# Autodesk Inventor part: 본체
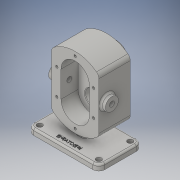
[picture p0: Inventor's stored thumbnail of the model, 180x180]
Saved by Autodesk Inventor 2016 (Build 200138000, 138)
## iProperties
Created: 2019-03
Part Number: 본체
Material: Generic
Document SubType Name: Modeling
Designer: Administrator
Density: 1 g/cm^3
Appearance: Default
Author: Administrator
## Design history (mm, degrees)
sketch "스케치1"
  geometry: L1 (60, 36.5)-(-60, 36.5); L2 (-60, 36.5)-(-60, -36.5); L3 (-60, -36.5)-(60, -36.5); L4 (60, -36.5)-(60, 36.5); L5 (60, 36.5)-(-60, -36.5); L6 (-60, 36.5)-(60, -36.5); 1 further point
  constraints: 12 end point, 2 midpoint, 2 parallel, 1 horizontal, 1 perpendicular
  dimensions: "d0" = 73 distance of L1.end L2.end; "d1" = 120 distance of L2.end L3.end
extrude "돌출1" new body sketch "스케치1" distance "d2" = 10; taper "d3" = 0 deg
node "작업 평면1"
sketch "스케치2"
  geometry: L1 (0, 0)-(0, 78); L2 (-40, 33.279)-(40, 33.279); L3 (40, 33.279)-(40, 122.721); L4 (-40, 122.721)-(-40, 33.279); L5 (-40, 33.279)-(40, 122.721); L6 (40, 33.279)-(-40, 122.721); L7 (-46.037, 78)-(46.038, 78); A1 r 60 centre (0, 78) between (40, 122.721) and (-40, 122.721); A2 r 60 centre (0, 78) between (-40, 33.279) and (40, 33.279); 2 further points
  constraints: 14 end point, 5 midpoint, 4 point on circle, 2 centre point, 2 horizontal, 1 coincident, 1 parallel, 1 perpendicular, 1 vertical
  dimensions: "d5" = 78 distance of L1.start L1.end; "d6" = 80 distance between parallel lines of L3 L4; "d7" = 60 radius of A1; "d8" = 60 radius of A2
extrude "돌출2" join sketch "스케치2" distance "d9" = 53; taper "d10" = 0 deg
sketch "스케치3"
  geometry: L1 (0, 0)-(0, 78); L2 (-54.769, 78)-(54.769, 78); L3 (0, 100)-(0, 56); L4 (-24, 100)-(-24, 56); L5 (24, 56)-(24, 100); A1 r 24 centre (0, 100) between (24, 100) and (-24, 100); A2 r 24 centre (0, 56) between (-24, 56) and (24, 56); 1 further point
  constraints: 12 end point, 4 point on circle, 4 tangent, 2 centre point, 2 midpoint, 1 coincident, 1 horizontal, 1 parallel, 1 point on line, 1 vertical
  dimensions: "d11" = 78 distance of L1.end L1.start; "d12" = 22 distance of L1.end L3.start; "d13" = 24 radius of A1
extrude "돌출3" cut sketch "스케치3" distance "d14" = 29; taper "d15" = 0 deg
sketch "스케치4"
  geometry: L1 (0, 0)-(0, 78); C1 r 12.5 at (0, 100); C2 r 12.5 at (0, 56)
  constraints: 2 centre point, 2 end point, 2 point on line, 1 equal radius, 1 vertical
  dimensions: "d16" = 78 distance of L1.start L1.end; "d17" = 22 distance of L1.end C1.centre; "d18" = 22 distance of L1.end C2.centre; "d19" = 25 diameter of C1
extrude "돌출4" cut sketch "스케치4" distance "d20" = 15; taper "d21" = 0 deg
sketch "스케치5"
  geometry: C1 r 12.5 at (0, 100) reference; C2 r 19 at (0, 100); 1 further point
  constraints: 1 centre point, 1 concentric
  dimensions: "d22" = 38 diameter of C2
extrude "돌출5" join sketch "스케치5" distance "d23" = 17; taper "d24" = 0 deg
fillet "모깎기1" dims "d29" = 10
fillet "모깎기2" dims "d30" = 3
sketch "스케치7"
  geometry: L1 (-50, 36.5)-(-50, 33.5) reference; L2 (-50, 33.5)-(50, 33.5) reference; L3 (50, 36.5)-(50, 33.5) reference; L4 (50, 36.5)-(-50, 36.5) reference; L5 (-6, 36.5)-(6, 36.5); L6 (6, 36.5)-(6, -6.5); L7 (6, -6.5)-(-6, -6.5); L8 (-6, -6.5)-(-6, 36.5); 1 further point
  constraints: 8 end point, 2 parallel, 1 horizontal, 1 perpendicular, 1 point on line
  dimensions: "d31" = 43 distance of L5.end L6.end; "d32" = 6 distance from line of point (0, 0) L6; "d33" = 6 distance from line of point (0, 0) L8
extrude "돌출6" join sketch "스케치7" stored distance "d34" = 7.3; taper "d35" = 0 deg; dims "d8" = 60
fillet "모깎기3" dims "d36" = 3
fillet "모깎기4" dims "d37" = 10
sketch "스케치8"
  geometry: L1 (81, -53.5)-(119, -53.5) reference; L2 (100, -53.5)-(100, -46.2); L3 (100, -46.2)-(114, -46.2); L4 (114, -46.2)-(114, -52.8); L5 (100, -53.5)-(114.404, -53.5); L6 (114, -52.8)-(114.404, -53.5); 1 further point
  constraints: 10 end point, 1 midpoint, 1 perpendicular, 1 vertical
  dimensions: "d38" = 7.3 distance of L2.start L2.end; "d39" = 14 distance of L2.end L3.end; "d42" = 30 deg angle of L6 L4; "d43" = 6.6 distance of L3.end L4.end
revolve "회전2" sketch "스케치8" stored, may be unused: angle "d44" = 90 deg
sketch "스케치9"
  geometry: C1 r 8.5 at (0, 0); C2 r 19 at (0, 0) reference; 1 further point
  constraints: 1 centre point, 1 concentric
  dimensions: "d45" = 17 diameter of C1
extrude "돌출7" cut sketch "스케치9" stored distance "d46" = 7.3; taper "d47" = 0 deg
chamfer "모따기1" distance "d48" = 1; stored, may be unused: second distance "d49" = 2, angle "d50" = 45 deg
chamfer "모따기2" distance "d51" = 1; stored, may be unused: second distance "d52" = 2, angle "d53" = 45 deg
hole "구멍1" diameter "d56" = 9; stored, may be unused: countersink angle "d60" = 90 deg, drill point angle "d62" = 0 deg; dims "d54" = 10, "d55" = 10, "d57" = 6, "d58" = 4, "d59" = 2, "d61" = 10
hole "구멍2" diameter "d65" = 9; stored, may be unused: countersink angle "d69" = 90 deg, drill point angle "d71" = 0 deg; dims "d63" = 10, "d64" = 10, "d66" = 6, "d67" = 4, "d68" = 2, "d70" = 10
hole "구멍3" diameter "d74" = 9; stored, may be unused: countersink angle "d78" = 90 deg, drill point angle "d80" = 0 deg; dims "d72" = 10, "d73" = 10, "d75" = 6, "d76" = 4, "d77" = 2, "d79" = 10
hole "구멍4" diameter "d83" = 9; stored, may be unused: countersink angle "d87" = 90 deg, drill point angle "d89" = 0 deg; dims "d81" = 10, "d82" = 10, "d84" = 6, "d85" = 4, "d86" = 2, "d88" = 10
fillet "모깎기5" dims "d90" = 3
feature "두껍게 하기1" dims "d91" = 2, "d92" = 2
feature "두껍게 하기2" dims "d93" = 1, "d94" = 1
fillet "모깎기6" dims "d95" = 3
sketch "스케치10"
  geometry: L1 (0, 0)-(0, 78); L2 (0, 100)-(0, 56); L3 (-31, 100)-(-31, 56); L4 (31, 56)-(31, 100); L5 (-31, 100)-(31, 100); L6 (-31, 56)-(31, 56); A1 r 31 centre (0, 100) between (31, 100) and (-31, 100); A2 r 31 centre (0, 56) between (-31, 56) and (31, 56); 9 further points
  constraints: 14 end point, 6 coincident, 6 point on circle, 4 tangent, 2 centre point, 2 horizontal, 1 midpoint, 1 parallel, 1 vertical, 1 vertical alignment, 1 other
  dimensions: "d96" = 78 distance of L1.start L1.end; "d97" = 31 radius of A1; "d98" = 44 distance of L2.end point (0, 100)
hole "구멍5" sketch "스케치10" at (0, 131), (0, 25), (-31, 56), (31, 56), (31, 100), (-31, 100) diameter "d99" = 4.134; stored, may be unused: countersink angle "d103" = 90 deg, drill point angle "d105" = 120 deg; dims "d100" = 10, "d101" = 4, "d102" = 2, "d104" = 12
sketch "스케치12"
  geometry: L1 (-50, -36.5)-(50, -36.5) reference; L2 (0, -36.5)-(0, -26.5); 2 further points
  constraints: 2 end point, 1 coincident, 1 midpoint, 1 vertical, 1 other
  dimensions: "d131" = 10 distance of L2.start L2.end
feature "엠보싱1" sketch "스케치12" dims "d132" = 0.5, "d133" = 0
sketch "스케치13"
  geometry: L1 (-53, 18)-(-53, 62) reference; L2 (-53, 40)-(-39, 40); C1 r 11 at (-39, 40); 1 further point
  constraints: 2 end point, 1 centre point, 1 coincident, 1 horizontal, 1 midpoint
  dimensions: "d134" = 14 distance of L2.start L2.end; "d135" = 22 diameter of C1
extrude "돌출8" join sketch "스케치13" distance "d136" = 8; taper "d137" = 0 deg
fillet "모깎기9" dims "d138" = 3
hole "구멍8" diameter "d141" = 8.376; stored, may be unused: countersink angle "d145" = 90 deg, drill point angle "d147" = 118 deg; dims "d139" = 10, "d140" = 10, "d142" = 20, "d143" = 4, "d144" = 2, "d146" = 27.3
hole "구멍9" diameter "d150" = 8.376; stored, may be unused: countersink angle "d154" = 90 deg, drill point angle "d156" = 118 deg; dims "d148" = 10, "d149" = 10, "d151" = 20, "d152" = 4, "d153" = 2, "d155" = 27.3
fillet "모깎기10" dims "d157" = 0.5
node "솔리드1"
mirror "대칭2"
node "투영된 루프1"
other parameters: "d4" = -36.5
